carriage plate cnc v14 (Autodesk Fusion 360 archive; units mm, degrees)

design "carriage plate cnc" references "Cup Holder"
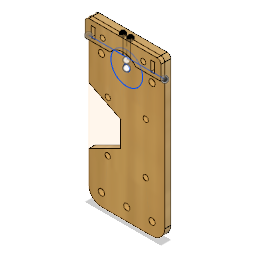
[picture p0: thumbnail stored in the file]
parameter "material" = 5
parameter "tool_dia" = 3.175
sketch "Sketch1" plane through (0, 0, 0) normal (0, 0, 1) x axis (1, 0, 0)
  line L1 (-20, 57.5) -> (20, 57.5)
  line L2 (-30, -47.5) -> (-30, 47.5)
  line L3 (20, -57.5) -> (-20, -57.5)
  line L4 (30, 47.5) -> (30, -47.5)
  line L5 (0, 22.5) -> (0, 1.75)
  line L6 (22.5, 0) -> (1.75, 0)
  circle C1 centre (0, 47.5) radius 2.46
  circle C2 centre (20, -47.5) radius 2.46
  circle C3 centre (0, -47.5) radius 2.46
  circle C4 centre (-20, -47.5) radius 2.46
  circle C5 centre (20, 47.5) radius 2.46
  circle C6 centre (-20, 47.5) radius 2.46
  arc A1 centre (20, 47.5) radius 10 clockwise from (20, 57.5) to (30, 47.5)
  arc A2 centre (-20, 47.5) radius 10 clockwise from (-30, 47.5) to (-20, 57.5)
  arc A3 centre (-20, -47.5) radius 10 clockwise from (-20, -57.5) to (-30, -47.5)
  arc A4 centre (20, -47.5) radius 10 clockwise from (30, -47.5) to (20, -57.5)
  circle C7 centre (-15, -20) radius 2
  circle C8 centre (15, -20) radius 2
  circle C9 centre (-15, 20) radius 2
  circle C10 centre (15, 20) radius 2
  point P1 (0, 0)
  point P2 (0, 0)
  point P4 (20, -47.5)
  point P5 (0, -47.5)
  point P6 (-20, -47.5)
  point P3 (0, 47.5)
  point P7 (20, 47.5)
  point P8 (-20, 47.5)
  point P9 (0, 0)
  point P10 (20, 57.5)
  point P16 (-30, -47.5)
  point P22 (-30, -47.5)
  point P23 (20, 57.5)
  point P24 (-15, -20)
  coincident P1 P2
  horizontal P4 P5
  horizontal P5 P6
  equal C2 C3
  equal C3 C4
  equal C4 C6
  equal C1 C6
  equal C1 C5
  vertical P2 P3
  horizontal P3 P7
  horizontal P3 P8
  vertical P1 P5
  vertical P4 P7
  vertical P6 P8
  perpendicular L1 L2
  parallel L1 L3
  parallel L2 L4
  horizontal L1
  coincident P1 P9
  tangent L4 A1
  coincident L1 P10
  tangent L2 A2
  tangent L3 A3
  coincident L2 P16
  tangent L3 A4
  coincident A3 P22
  coincident A1 P23
  tangent L1 A2
  tangent L1 A1
  tangent L4 A4
  tangent L2 A3
  equal A3 A4
  equal A1 A4
  equal A1 A2
  symmetric C7 L5 C8
  symmetric C7 L6 C9
  symmetric C8 L6 C10
  dimension "d3_1" distance P2 P3 = 47.5 (= "( 95 / 2 ) * 1 mm")
  dimension "d4_1" distance P1 P5 = 47.5 (= "d3_1")
  dimension "d5_1" distance P4 P5 = 20
  dimension "d6_1" distance P5 P6 = 20 (= "d5_1")
  dimension "d7" diameter C1 = 4.92
  dimension "d8_1" distance P7 L1 = 10
  dimension "d9_1" distance P7 L4 = 10
  dimension "d10_1" distance P4 L3 = 10 (= "d8_1")
  dimension "d12_1" distance P6 L2 = 10 (= "d8_1")
  dimension "d13_1" radius A2 = 10
  dimension "d18_1" diameter C7 = 4
  dimension "d22" distance P9 P24 = 20
  dimension "d23" distance P2 P24 = 15
extrude "Extrude1" new body sketch "Sketch1" profile of C1 C2 C3 C4 C5 C6 L1 L2 L3 L4 A1 A2 A3 A4 C7 C8 C9 C10 along normal blind 5
sketch "Sketch1" plane through (0, 0, 5) normal (0, 0, 1) x axis (-1, 0, 0)
  line L1 (-30, -47.5) -> (-30, 47.5)
  line L2 (20, -57.5) -> (-20, -57.5)
  line L3 (30, 47.5) -> (30, -47.5)
  line L4 (-20, 57.5) -> (20, 57.5)
  line L5 (24.7343, -47.5) -> (22.3671, -51.6)
  line L6 (22.3671, -43.4) -> (24.7343, -47.5)
  line L7 (17.6329, -43.4) -> (22.3671, -43.4)
  line L8 (15.2657, -47.5) -> (17.6329, -43.4)
  line L9 (17.6329, -51.6) -> (15.2657, -47.5)
  line L10 (22.3671, -51.6) -> (17.6329, -51.6)
  line L11 (4.7343, -47.5) -> (2.3671, -51.6)
  line L12 (2.3671, -43.4) -> (4.7343, -47.5)
  line L13 (-2.3671, -43.4) -> (2.3671, -43.4)
  line L14 (-4.7343, -47.5) -> (-2.3671, -43.4)
  line L15 (-2.3671, -51.6) -> (-4.7343, -47.5)
  line L16 (2.3671, -51.6) -> (-2.3671, -51.6)
  line L17 (-15.2657, -47.5) -> (-17.6329, -51.6)
  line L18 (-17.6329, -43.4) -> (-15.2657, -47.5)
  line L19 (-22.3671, -43.4) -> (-17.6329, -43.4)
  line L20 (-24.7343, -47.5) -> (-22.3671, -43.4)
  line L21 (-22.3671, -51.6) -> (-24.7343, -47.5)
  line L22 (-17.6329, -51.6) -> (-22.3671, -51.6)
  line L23 (24.7343, 47.5) -> (22.3671, 43.4)
  line L24 (22.3671, 51.6) -> (24.7343, 47.5)
  line L25 (17.6329, 51.6) -> (22.3671, 51.6)
  line L26 (15.2657, 47.5) -> (17.6329, 51.6)
  line L27 (17.6329, 43.4) -> (15.2657, 47.5)
  line L28 (22.3671, 43.4) -> (17.6329, 43.4)
  line L29 (4.7343, 47.5) -> (2.3671, 43.4)
  line L30 (2.3671, 51.6) -> (4.7343, 47.5)
  line L31 (-2.3671, 51.6) -> (2.3671, 51.6)
  line L32 (-4.7343, 47.5) -> (-2.3671, 51.6)
  line L33 (-2.3671, 43.4) -> (-4.7343, 47.5)
  line L34 (2.3671, 43.4) -> (-2.3671, 43.4)
  line L35 (-15.2657, 47.5) -> (-17.6329, 43.4)
  line L36 (-17.6329, 51.6) -> (-15.2657, 47.5)
  line L37 (-22.3671, 51.6) -> (-17.6329, 51.6)
  line L38 (-24.7343, 47.5) -> (-22.3671, 51.6)
  line L39 (-22.3671, 43.4) -> (-24.7343, 47.5)
  line L40 (-17.6329, 43.4) -> (-22.3671, 43.4)
  circle C1 centre (0, 47.5) radius 2.46
  circle C2 centre (0, -47.5) radius 2.46
  circle C3 centre (-20, 47.5) radius 2.46
  circle C4 centre (20, 47.5) radius 2.46
  circle C5 centre (-15, -20) radius 2
  circle C6 centre (15, 20) radius 2
  circle C7 centre (20, -47.5) radius 2.46
  circle C8 centre (15, -20) radius 2
  circle C9 centre (-15, 20) radius 2
  circle C10 centre (-20, -47.5) radius 2.46
  arc A1 centre (-20, 47.5) radius 10 clockwise from (-30, 47.5) to (-20, 57.5)
  arc A2 centre (-20, -47.5) radius 10 clockwise from (-20, -57.5) to (-30, -47.5)
  arc A3 centre (20, -47.5) radius 10 clockwise from (30, -47.5) to (20, -57.5)
  arc A4 centre (20, 47.5) radius 10 clockwise from (20, 57.5) to (30, 47.5)
  point P8 (20, -47.5)
  point P26 (20, -47.5)
  point P3 (0, -47.5)
  point P33 (0, -47.5)
  point P11 (-20, -47.5)
  point P40 (-20, -47.5)
  point P5 (20, 47.5)
  point P47 (20, 47.5)
  point P2 (0, 47.5)
  point P54 (0, 47.5)
  point P4 (-20, 47.5)
  point P61 (-20, 47.5)
  coincident P8 P26
  coincident P3 P33
  coincident P11 P40
  coincident P5 P47
  coincident P2 P54
  coincident P4 P61
  dimension "d1" distance P26 L10 = 4.1
  dimension "d2" distance P33 L16 = 4.1 (= "d1")
  dimension "d3" distance P40 L22 = 4.1 (= "d2")
  dimension "d4" distance P47 L28 = 4.1 (= "d1")
  dimension "d5" distance P54 L34 = 4.1 (= "d1")
  dimension "d6" distance P61 L40 = 4.1 (= "d1")
extrude "Extrude1" new body sketch "Sketch1" profile of C5 C6 C8 C9 A1 L1 A2 L2 A3 L3 A4 L4 L5 L6 L7 L8 L9 L10 L11 L12 L13 L14 L15 L16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 along normal blind 5 (= "material")
extrude "Extrude2" add sketch "Sketch1" profile of C1 C2 C3 C4 C7 C10 L5 L6 L7 L8 L9 L10 L11 L12 L13 L14 L15 L16 L17 L18 L19 L20 L21 L22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 along normal blind 1
extrude "Extrude3" add sketch "Sketch1" profile of C5 C6 C8 C9 along normal blind 1
sketch "Sketch2" plane through (0, 0, 10) normal (0, 0, 1) x axis (1, 0, 0)
  line L1 (22.3671, 51.6) -> (17.6329, 51.6)
  line L2 (24.7343, 47.5) -> (22.3671, 51.6)
  line L3 (22.3671, 43.4) -> (24.7343, 47.5)
  line L4 (17.6329, 43.4) -> (22.3671, 43.4)
  line L5 (15.2657, 47.5) -> (17.6329, 43.4)
  line L6 (17.6329, 51.6) -> (15.2657, 47.5)
  line L7 (-17.6329, 51.6) -> (-22.3671, 51.6)
  line L8 (-15.2657, 47.5) -> (-17.6329, 51.6)
  line L9 (-17.6329, 43.4) -> (-15.2657, 47.5)
  line L10 (-22.3671, 43.4) -> (-17.6329, 43.4)
  line L11 (-24.7343, 47.5) -> (-22.3671, 43.4)
  line L12 (-22.3671, 51.6) -> (-24.7343, 47.5)
  line L13 (22.3671, -43.4) -> (17.6329, -43.4)
  line L14 (24.7343, -47.5) -> (22.3671, -43.4)
  line L15 (22.3671, -51.6) -> (24.7343, -47.5)
  line L16 (17.6329, -51.6) -> (22.3671, -51.6)
  line L17 (15.2657, -47.5) -> (17.6329, -51.6)
  line L18 (17.6329, -43.4) -> (15.2657, -47.5)
  line L19 (-17.6329, -43.4) -> (-22.3671, -43.4)
  line L20 (-15.2657, -47.5) -> (-17.6329, -43.4)
  line L21 (-17.6329, -51.6) -> (-15.2657, -47.5)
  line L22 (-22.3671, -51.6) -> (-17.6329, -51.6)
  line L23 (-24.7343, -47.5) -> (-22.3671, -51.6)
  line L24 (-22.3671, -43.4) -> (-24.7343, -47.5)
  line L25 (2.3671, -43.4) -> (-2.3671, -43.4)
  line L26 (4.7343, -47.5) -> (2.3671, -43.4)
  line L27 (2.3671, -51.6) -> (4.7343, -47.5)
  line L28 (-2.3671, -51.6) -> (2.3671, -51.6)
  line L29 (-4.7343, -47.5) -> (-2.3671, -51.6)
  line L30 (-2.3671, -43.4) -> (-4.7343, -47.5)
  line L31 (2.3671, 51.6) -> (-2.3671, 51.6)
  line L32 (4.7343, 47.5) -> (2.3671, 51.6)
  line L33 (2.3671, 43.4) -> (4.7343, 47.5)
  line L34 (-2.3671, 43.4) -> (2.3671, 43.4)
  line L35 (-4.7343, 47.5) -> (-2.3671, 43.4)
  line L36 (-2.3671, 51.6) -> (-4.7343, 47.5)
  line L37 (20, -57.5) -> (-20, -57.5)
  line L38 (30, 47.5) -> (30, -47.5)
  line L39 (-20, 57.5) -> (20, 57.5)
  line L40 (-30, -47.5) -> (-30, 47.5)
  line L41 (30, 30) -> (-30, 30)
  line L42 (30, -30) -> (-30, -30)
  circle C1 centre (-15, 20) radius 2
  circle C2 centre (15, 20) radius 2
  circle C3 centre (-15, -20) radius 2
  circle C4 centre (15, -20) radius 2
  arc A1 centre (20, -47.5) radius 10 clockwise from (30, -47.5) to (20, -57.5)
  arc A2 centre (20, 47.5) radius 10 clockwise from (20, 57.5) to (30, 47.5)
  arc A3 centre (-20, 47.5) radius 10 clockwise from (-30, 47.5) to (-20, 57.5)
  arc A4 centre (-20, -47.5) radius 10 clockwise from (-20, -57.5) to (-30, -47.5)
  point P54 (-30, 30)
  point P55 (30, 30)
  point P56 (-30, -30)
  point P57 (30, -30)
  point P1 (0, 0)
  coincident L40 P54
  coincident L38 P55
  perpendicular L38 L41
  coincident L40 P56
  coincident L38 P57
  perpendicular L38 L42
  dimension "d15" distance P1 L42 = 30
  dimension "d16" distance P1 L41 = 30
extrude "Extrude4" add sketch "Sketch2" profile of L20 C1 C2 C3 C4 against normal blind 4
sketch "Sketch3" plane through (0, 0, 0) normal (0, 0, -1) x axis (1, 0, 0)
  line L1 (-20, 57.5) -> (20, 57.5)
  line L2 (-30, -47.5) -> (-30, 47.5)
  line L3 (20, -57.5) -> (-20, -57.5)
  line L4 (30, 47.5) -> (30, -47.5)
  circle C1 centre (0, 47.5) radius 2.46
  circle C2 centre (0, -47.5) radius 2.46
  circle C3 centre (20, 47.5) radius 2.46
  circle C4 centre (-20, 47.5) radius 2.46
  circle C5 centre (15, -20) radius 2
  circle C6 centre (-15, 20) radius 2
  circle C7 centre (-20, -47.5) radius 2.46
  circle C8 centre (-15, -20) radius 2
  circle C9 centre (15, 20) radius 2
  circle C10 centre (20, -47.5) radius 2.46
  arc A1 centre (20, 47.5) radius 10 clockwise from (20, 57.5) to (30, 47.5)
  arc A2 centre (-20, 47.5) radius 10 clockwise from (-30, 47.5) to (-20, 57.5)
  arc A3 centre (-20, -47.5) radius 10 clockwise from (-20, -57.5) to (-30, -47.5)
  arc A4 centre (20, -47.5) radius 10 clockwise from (30, -47.5) to (20, -57.5)
extrude "Extrude5" new body sketch "Sketch3" profile of C5 C6 C8 C9 against normal blind 1
combine "Combine1"
sketch "Sketch4" plane through (0, 0, 5) normal (0, 0, 1) x axis (-1, 0, 0)
  circle C1 centre (15, -20) radius 2.1
  circle C2 centre (-15, -20) radius 2.1
  circle C3 centre (15, 20) radius 2.1
  circle C4 centre (-15, 20) radius 2.1
  dimension "d21" diameter C1 = 4.2
  dimension "d26" diameter C2 = 4.2
  dimension "d27" diameter C3 = 4.2
  dimension "d28" diameter C4 = 4.2
extrude "Extrude6" cut sketch "Sketch4" + "Sketch1" profile of S2:C5 S1:C1 S1:C3 S1:C4 blind -4
extrude "Extrude7" cut sketch "Sketch4" profile of C2 against normal blind 4
sketch "Sketch5" plane through (0, 0, 5) normal (0, 0, 1) x axis (1, 0, 0)
  line L1 (30, 47.5) -> (30, -47.5)
  line L2 (-20, 57.5) -> (20, 57.5)
  line L3 (-30, -47.5) -> (-30, 47.5)
  line L4 (20, -57.5) -> (-20, -57.5)
  line L5 (-30, 47.5) -> (30, 47.5)
  line L6 (-30, 69.5) -> (-30, 47.5)
  line L7 (30, 69.5) -> (-30, 69.5)
  line L8 (30, 47.5) -> (30, 69.5)
  line L9 (25, 65.5) -> (22, 65.5)
  line L10 (25, 57.5) -> (25, 65.5)
  line L11 (22, 57.5) -> (25, 57.5)
  line L12 (22, 65.5) -> (22, 57.5)
  line L13 (0, 57.5) -> (0, 69.5)
  line L14 (-25, 57.5) -> (-25, 65.5)
  line L15 (-22, 57.5) -> (-25, 57.5)
  line L16 (-25, 65.5) -> (-22, 65.5)
  line L17 (-22, 65.5) -> (-22, 57.5)
  line L18 (4, 57.5) -> (10, 57.5)
  line L19 (4, 65.5) -> (4, 57.5)
  line L20 (10, 65.5) -> (4, 65.5)
  line L21 (10, 57.5) -> (10, 65.5)
  line L22 (22, 61.5) -> (10, 61.5)
  line L23 (-4, 65.5) -> (-4, 57.5)
  line L24 (-10, 65.5) -> (-4, 65.5)
  line L25 (-4, 57.5) -> (-10, 57.5)
  line L26 (-10, 57.5) -> (-10, 65.5)
  circle C1 centre (15, 20) radius 2.1
  circle C2 centre (-15, 20) radius 2.1
  circle C3 centre (-15, -20) radius 2.1
  circle C4 centre (15, -20) radius 2.1
  circle C5 centre (0, -47.5) radius 2.46
  circle C6 centre (20, -47.5) radius 2.46
  circle C7 centre (0, 47.5) radius 2.46
  circle C8 centre (-20, -47.5) radius 2.46
  circle C9 centre (20, 47.5) radius 2.46
  circle C10 centre (-20, 47.5) radius 2.46
  arc A1 centre (20, -47.5) radius 10 clockwise from (30, -47.5) to (20, -57.5)
  arc A2 centre (20, 47.5) radius 10 clockwise from (20, 57.5) to (30, 47.5)
  arc A3 centre (-20, 47.5) radius 10 clockwise from (-30, 47.5) to (-20, 57.5)
  arc A4 centre (-20, -47.5) radius 10 clockwise from (-20, -57.5) to (-30, -47.5)
  circle C11 centre (16, 61.5) radius 2
  circle C12 centre (-16, 61.5) radius 2
  point P14 (30, 47.5)
  point P20 (30, 47.5)
  point P28 (0, 69.5)
  point P29 (0, 57.5)
  point P24 (22, 65.5)
  point P33 (-22, 65.5)
  point P25 (25, 65.5)
  point P30 (-25, 65.5)
  point P26 (25, 57.5)
  point P31 (-25, 57.5)
  point P27 (22, 57.5)
  point P32 (-22, 57.5)
  point P34 (10, 57.5)
  point P38 (10, 61.5)
  point P39 (22, 61.5)
  point P40 (16, 61.5)
  point P45 (-10, 57.5)
  point P35 (4, 57.5)
  point P42 (-4, 57.5)
  point P36 (4, 65.5)
  point P43 (-4, 65.5)
  point P37 (10, 65.5)
  point P44 (-10, 65.5)
  point P23 (30, 69.5)
  horizontal L5
  vertical L6
  horizontal L7
  vertical L8
  coincident P14 P20
  collinear L3 L6
  horizontal L9
  vertical L10
  horizontal L11
  vertical L12
  collinear L2 L11
  midpoint L7 P28
  midpoint L2 P29
  symmetric P24 L13 P33
  symmetric P25 L13 P30
  symmetric P26 L13 P31
  symmetric P27 L13 P32
  horizontal L18
  vertical L19
  horizontal L20
  vertical L21
  coincident L2 P34
  midpoint L21 P38
  midpoint L12 P39
  midpoint L22 P40
  symmetric L13 P34 P45
  symmetric L13 P35 P42
  symmetric L13 P36 P43
  symmetric L13 P37 P44
  symmetric L13 C11 C12
  dimension "d33" distance P20 P23 = 22
  dimension "d34" distance P24 P25 = 3
  dimension "d35" distance P24 P27 = 8
  dimension "d36" distance L8 L10 = 5
  dimension "d37" distance P34 P35 = 6
  dimension "d38" distance P34 P37 = 8
  dimension "d39" distance L12 L21 = 12
  dimension "d40" diameter C11 = 4
extrude "Extrude8" add sketch "Sketch5" profile of A2 L2 A3 L6 L7 L8 L9 L10 L11 L12 L14 L15 L16 L17 L19 L20 L21 C11 C12 L23 L24 L26 against normal blind 5
fillet "Fillet1" radius 3
sketch "Sketch6" plane through (0, 0, 5) normal (0, 0, 1) x axis (1, 0, 0)
  line L1 (-30, -47.5) -> (-30, 66.5)
  line L2 (20, -57.5) -> (-20, -57.5)
  line L3 (30, 66.5) -> (30, -47.5)
  line L4 (-27, 69.5) -> (27, 69.5)
  line L5 (4, 57.5) -> (10, 57.5)
  line L6 (4, 65.5) -> (4, 57.5)
  line L7 (10, 65.5) -> (4, 65.5)
  line L8 (10, 57.5) -> (10, 65.5)
  line L9 (-22, 57.5) -> (-22, 65.5)
  line L10 (-25, 57.5) -> (-22, 57.5)
  line L11 (-25, 65.5) -> (-25, 57.5)
  line L12 (-22, 65.5) -> (-25, 65.5)
  line L13 (22, 57.5) -> (25, 57.5)
  line L14 (22, 65.5) -> (22, 57.5)
  line L15 (25, 65.5) -> (22, 65.5)
  line L16 (25, 57.5) -> (25, 65.5)
  line L17 (-10, 65.5) -> (-10, 57.5)
  line L18 (-4, 65.5) -> (-10, 65.5)
  line L19 (-4, 57.5) -> (-4, 65.5)
  line L20 (-10, 57.5) -> (-4, 57.5)
  line L21 (-3, 54.8814) -> (-30, 54.8814)
  line L22 (-3, 69.5) -> (-3, 54.8814)
  line L23 (3, 54.8814) -> (3, 69.5)
  line L24 (30, 54.8814) -> (3, 54.8814)
  line L25 (0, 53) -> (0, 69.5)
  line L26 (-3, 54.8814) -> (3, 54.8814)
  arc A1 centre (-27, 66.5) radius 3 clockwise from (-30, 66.5) to (-27, 69.5)
  arc A2 centre (-20, -47.5) radius 10 clockwise from (-20, -57.5) to (-30, -47.5)
  arc A3 centre (20, -47.5) radius 10 clockwise from (30, -47.5) to (20, -57.5)
  arc A4 centre (27, 66.5) radius 3 clockwise from (27, 69.5) to (30, 66.5)
  circle C1 centre (-16, 61.5) radius 2
  circle C2 centre (16, 61.5) radius 2
  circle C3 centre (15, 20) radius 2.1
  circle C4 centre (-15, 20) radius 2.1
  circle C5 centre (-15, -20) radius 2.1
  circle C6 centre (15, -20) radius 2.1
  circle C7 centre (0, -47.5) radius 2.46
  circle C8 centre (20, -47.5) radius 2.46
  circle C9 centre (0, 47.5) radius 2.46
  circle C10 centre (-20, -47.5) radius 2.46
  circle C11 centre (20, 47.5) radius 2.46
  circle C12 centre (-20, 47.5) radius 2.46
  point P40 (-30, 54.8814)
  point P42 (-3, 69.5)
  point P43 (3, 69.5)
  point P45 (30, 54.8814)
  point P46 (0, 69.5)
  coincident L1 P40
  perpendicular L1 L21
  coincident L4 P42
  perpendicular L4 L22
  coincident L4 P43
  perpendicular L4 L23
  coincident L3 P45
  perpendicular L3 L24
  midpoint L4 P46
  perpendicular L4 L25
  perpendicular L22 L26
  dimension "d44" distance L1 L22 = 27
  dimension "d45" distance L3 L23 = 27
extrude "Extrude9" new body sketch "Sketch6" profile of A1 L1 L3 A4 L4 L5 L6 L7 L8 L9 L10 L11 L12 C1 L13 L14 L15 L16 C2 L17 L18 L19 L20 L21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 along normal blind 5
sketch "Sketch1" plane through (0, 0, 10) normal (0, 0, 1) x axis (1, 0, 0)
  line L1 (10, 65.5) -> (4, 65.5)
  line L2 (10, 57.5) -> (10, 65.5)
  line L3 (4, 57.5) -> (10, 57.5)
  line L4 (4, 65.5) -> (4, 57.5)
  line L5 (-4, 57.5) -> (-4, 65.5)
  line L6 (-10, 57.5) -> (-4, 57.5)
  line L7 (-10, 65.5) -> (-10, 57.5)
  line L8 (-4, 65.5) -> (-10, 65.5)
  line L9 (25, 65.5) -> (22, 65.5)
  line L10 (25, 57.5) -> (25, 65.5)
  line L11 (22, 57.5) -> (25, 57.5)
  line L12 (22, 65.5) -> (22, 57.5)
  line L13 (-25, 65.5) -> (-25, 57.5)
  line L14 (-22, 65.5) -> (-25, 65.5)
  line L15 (-22, 57.5) -> (-22, 65.5)
  line L16 (-25, 57.5) -> (-22, 57.5)
  line L17 (30, 66.5) -> (30, 54.8814)
  line L18 (-27, 69.5) -> (27, 69.5)
  line L19 (-30, 54.8814) -> (-30, 66.5)
  line L20 (30, 54.8814) -> (-30, 54.8814)
  circle C1 centre (16, 61.5) radius 2
  circle C2 centre (-16, 61.5) radius 2
  arc A1 centre (27, 66.5) radius 3 clockwise from (27, 69.5) to (30, 66.5)
  arc A2 centre (-27, 66.5) radius 3 clockwise from (-30, 66.5) to (-27, 69.5)
sketch "Sketch2" plane through (0, 0, 5) normal (0, 0, 1) x axis (1, 0, 0)
  line L1 (-30, -47.5) -> (-30, 66.5)
  line L2 (20, -57.5) -> (-20, -57.5)
  line L3 (30, 66.5) -> (30, -47.5)
  line L4 (-27, 69.5) -> (27, 69.5)
  line L5 (4, 57.5) -> (10, 57.5)
  line L6 (4, 65.5) -> (4, 57.5)
  line L7 (10, 65.5) -> (4, 65.5)
  line L8 (10, 57.5) -> (10, 65.5)
  line L9 (22, 57.5) -> (25, 57.5)
  line L10 (22, 65.5) -> (22, 57.5)
  line L11 (25, 65.5) -> (22, 65.5)
  line L12 (25, 57.5) -> (25, 65.5)
  line L13 (-22, 57.5) -> (-22, 65.5)
  line L14 (-25, 57.5) -> (-22, 57.5)
  line L15 (-25, 65.5) -> (-25, 57.5)
  line L16 (-22, 65.5) -> (-25, 65.5)
  line L17 (-10, 65.5) -> (-10, 57.5)
  line L18 (-4, 65.5) -> (-10, 65.5)
  line L19 (-4, 57.5) -> (-4, 65.5)
  line L20 (-10, 57.5) -> (-4, 57.5)
  arc A1 centre (-27, 66.5) radius 3 clockwise from (-30, 66.5) to (-27, 69.5)
  arc A2 centre (-20, -47.5) radius 10 clockwise from (-20, -57.5) to (-30, -47.5)
  arc A3 centre (20, -47.5) radius 10 clockwise from (30, -47.5) to (20, -57.5)
  arc A4 centre (27, 66.5) radius 3 clockwise from (27, 69.5) to (30, 66.5)
  circle C1 centre (16, 61.5) radius 2
  circle C2 centre (-16, 61.5) radius 2
  circle C3 centre (15, 20) radius 2.1
  circle C4 centre (-15, 20) radius 2.1
  circle C5 centre (-15, -20) radius 2.1
  circle C6 centre (15, -20) radius 2.1
  circle C7 centre (0, -47.5) radius 2.46
  circle C8 centre (20, -47.5) radius 2.46
  circle C9 centre (0, 47.5) radius 2.46
  circle C10 centre (-20, -47.5) radius 2.46
  circle C11 centre (20, 47.5) radius 2.46
  circle C12 centre (-20, 47.5) radius 2.46
component_insert "Component Insert"
sketch "Sketch3" plane through (0, 0, -4) normal (0, 0, 1) x axis (-1, 0, 0)
  line L1 (30, 22.5) -> (5, 10)
  line L2 (30, 47.5) -> (30, 22.5)
  line L3 (-20, 57.5) -> (20, 57.5)
  line L4 (-30, -47.5) -> (-30, 47.5)
  line L5 (20, -57.5) -> (-20, -57.5)
  line L6 (30, -22.5) -> (30, -47.5)
  line L7 (5, -10) -> (30, -22.5)
  line L8 (5, 10) -> (5, -10)
  circle C1 centre (0, -47.5) radius 2.46
  circle C2 centre (20, -47.5) radius 2.46
  circle C3 centre (-20, 47.5) radius 2.46
  circle C4 centre (0, 47.5) radius 2.46
  circle C5 centre (-20, -47.5) radius 2.46
  circle C6 centre (20, 47.5) radius 2.46
  arc A1 centre (20, 47.5) radius 10 clockwise from (20, 57.5) to (30, 47.5)
  arc A2 centre (-20, 47.5) radius 10 clockwise from (-30, 47.5) to (-20, 57.5)
  arc A3 centre (-20, -47.5) radius 10 clockwise from (-20, -57.5) to (-30, -47.5)
  arc A4 centre (20, -47.5) radius 10 clockwise from (30, -47.5) to (20, -57.5)
sketch "Sketch4" plane through (0, 0, -4) normal (0, 0, 1) x axis (-1, 0, 0)
  line L1 (30, 22.5) -> (5, 10)
  line L2 (30, 47.5) -> (30, 22.5)
  line L3 (-20, 57.5) -> (20, 57.5)
  line L4 (-30, -47.5) -> (-30, 47.5)
  line L5 (20, -57.5) -> (-20, -57.5)
  line L6 (30, -22.5) -> (30, -47.5)
  line L7 (5, -10) -> (30, -22.5)
  line L8 (5, 10) -> (5, -10)
  line L9 (30, 22.5) -> (30, -22.5)
  circle C1 centre (0, -47.5) radius 2.46
  circle C2 centre (20, -47.5) radius 2.46
  circle C3 centre (-20, 47.5) radius 2.46
  circle C4 centre (0, 47.5) radius 2.46
  circle C5 centre (-20, -47.5) radius 2.46
  circle C6 centre (20, 47.5) radius 2.46
  arc A1 centre (20, 47.5) radius 10 clockwise from (20, 57.5) to (30, 47.5)
  arc A2 centre (-20, 47.5) radius 10 clockwise from (-30, 47.5) to (-20, 57.5)
  arc A3 centre (-20, -47.5) radius 10 clockwise from (-20, -57.5) to (-30, -47.5)
  arc A4 centre (20, -47.5) radius 10 clockwise from (30, -47.5) to (20, -57.5)
  point P18 (30, -22.5)
  point P20 (30, -22.5)
  point P9 (30, 22.5)
  point P21 (30, 22.5)
  coincident P18 P20
  coincident P9 P21
extrude "Extrude10" cut sketch "Sketch4" profile of L1 L7 L8 L9 along normal blind 35
sketch "Sketch5" plane through (0, 0, 5) normal (0, 0, 1) x axis (1, 0, 0)
  line L1 (-10, 65.5) -> (-10, 57.5)
  line L2 (-4, 65.5) -> (-10, 65.5)
  line L3 (-4, 57.5) -> (-4, 65.5)
  line L4 (-10, 57.5) -> (-4, 57.5)
  line L5 (-22, 57.5) -> (-22, 65.5)
  line L6 (-25, 57.5) -> (-22, 57.5)
  line L7 (-25, 65.5) -> (-25, 57.5)
  line L8 (-22, 65.5) -> (-25, 65.5)
  line L9 (22, 57.5) -> (25, 57.5)
  line L10 (22, 65.5) -> (22, 57.5)
  line L11 (25, 65.5) -> (22, 65.5)
  line L12 (25, 57.5) -> (25, 65.5)
  line L13 (4, 57.5) -> (10, 57.5)
  line L14 (4, 65.5) -> (4, 57.5)
  line L15 (10, 65.5) -> (4, 65.5)
  line L16 (10, 57.5) -> (10, 65.5)
  line L17 (-5, 10) -> (-30, 22.5)
  line L18 (-5, -10) -> (-5, 10)
  line L19 (-30, -22.5) -> (-5, -10)
  line L20 (-30, -47.5) -> (-30, -22.5)
  line L21 (20, -57.5) -> (-20, -57.5)
  line L22 (30, 66.5) -> (30, -47.5)
  line L23 (-27, 69.5) -> (27, 69.5)
  line L24 (-30, 22.5) -> (-30, 66.5)
  circle C1 centre (-20, 47.5) radius 2.46
  circle C2 centre (20, 47.5) radius 2.46
  circle C3 centre (-20, -47.5) radius 2.46
  circle C4 centre (0, 47.5) radius 2.46
  circle C5 centre (20, -47.5) radius 2.46
  circle C6 centre (0, -47.5) radius 2.46
  circle C7 centre (15, -20) radius 2.1
  circle C8 centre (-15, -20) radius 2.1
  circle C9 centre (-15, 20) radius 2.1
  circle C10 centre (15, 20) radius 2.1
  circle C11 centre (-16, 61.5) radius 2
  circle C12 centre (16, 61.5) radius 2
  arc A1 centre (-20, -47.5) radius 10 clockwise from (-20, -57.5) to (-30, -47.5)
  arc A2 centre (20, -47.5) radius 10 clockwise from (30, -47.5) to (20, -57.5)
  arc A3 centre (27, 66.5) radius 3 clockwise from (27, 69.5) to (30, 66.5)
  arc A4 centre (-27, 66.5) radius 3 clockwise from (-30, 66.5) to (-27, 69.5)
sketch "Sketch6" plane through (0, 0, 5) normal (0, 0, 1) x axis (1, 0, 0)
  line L1 (-10, 65.5) -> (-10, 57.5)
  line L2 (-4, 65.5) -> (-10, 65.5)
  line L3 (-4, 57.5) -> (-4, 65.5)
  line L4 (-10, 57.5) -> (-4, 57.5)
  line L5 (-22, 57.5) -> (-22, 65.5)
  line L6 (-25, 57.5) -> (-22, 57.5)
  line L7 (-25, 65.5) -> (-25, 57.5)
  line L8 (-22, 65.5) -> (-25, 65.5)
  line L9 (22, 57.5) -> (25, 57.5)
  line L10 (22, 65.5) -> (22, 57.5)
  line L11 (25, 65.5) -> (22, 65.5)
  line L12 (25, 57.5) -> (25, 65.5)
  line L13 (4, 57.5) -> (10, 57.5)
  line L14 (4, 65.5) -> (4, 57.5)
  line L15 (10, 65.5) -> (4, 65.5)
  line L16 (10, 57.5) -> (10, 65.5)
  line L17 (-5, 10) -> (-30, 22.5)
  line L18 (-5, -10) -> (-5, 10)
  line L19 (-30, -22.5) -> (-5, -10)
  line L20 (-30, -47.5) -> (-30, -22.5)
  line L21 (20, -57.5) -> (-20, -57.5)
  line L22 (30, 66.5) -> (30, -47.5)
  line L23 (-27, 69.5) -> (27, 69.5)
  line L24 (-30, 22.5) -> (-30, 66.5)
  line L25 (30, 54.8814) -> (3, 54.8814)
  line L26 (-3, 54.8814) -> (3, 54.8814)
  line L27 (-3, 54.8814) -> (-30, 54.8814)
  circle C1 centre (-20, 47.5) radius 2.46
  circle C2 centre (20, 47.5) radius 2.46
  circle C3 centre (-20, -47.5) radius 2.46
  circle C4 centre (0, 47.5) radius 2.46
  circle C5 centre (20, -47.5) radius 2.46
  circle C6 centre (0, -47.5) radius 2.46
  circle C7 centre (15, -20) radius 2.1
  circle C8 centre (-15, -20) radius 2.1
  circle C9 centre (-15, 20) radius 2.1
  circle C10 centre (15, 20) radius 2.1
  circle C11 centre (-16, 61.5) radius 2
  circle C12 centre (16, 61.5) radius 2
  arc A1 centre (-20, -47.5) radius 10 clockwise from (-20, -57.5) to (-30, -47.5)
  arc A2 centre (20, -47.5) radius 10 clockwise from (30, -47.5) to (20, -57.5)
  arc A3 centre (27, 66.5) radius 3 clockwise from (27, 69.5) to (30, 66.5)
  arc A4 centre (-27, 66.5) radius 3 clockwise from (-30, 66.5) to (-27, 69.5)
  circle C13 centre (0, 47.5) radius 2.46
  circle C14 centre (0, 47.5) radius 12.5
  concentric C13 C14
  dimension "d51" diameter C14 = 25
extrude "Extrude11" cut sketch "Sketch6" profile of L3 L4 C4 L13 L14 C13 C14 along normal blind 10
sketch "Sketch7" plane through (0, 0, 10) normal (0, 0, 1) x axis (1, 0, 0)
  line L1 (4, 65.5) -> (4, 59.3427)
  line L2 (10, 65.5) -> (4, 65.5)
  line L3 (10, 57.5) -> (10, 65.5)
  line L4 (7.5, 57.5) -> (10, 57.5)
  line L5 (30, 54.8814) -> (10.0878, 54.8814)
  line L6 (30, 66.5) -> (30, 54.8814)
  line L7 (-27, 69.5) -> (27, 69.5)
  line L8 (-30, 54.8814) -> (-30, 66.5)
  line L9 (-10.0878, 54.8814) -> (-30, 54.8814)
  line L10 (-10, 57.5) -> (-7.5, 57.5)
  line L11 (-10, 65.5) -> (-10, 57.5)
  line L12 (-4, 65.5) -> (-10, 65.5)
  line L13 (-4, 59.3427) -> (-4, 65.5)
  line L14 (-25, 65.5) -> (-25, 57.5)
  line L15 (-22, 65.5) -> (-25, 65.5)
  line L16 (-22, 57.5) -> (-22, 65.5)
  line L17 (-25, 57.5) -> (-22, 57.5)
  line L18 (25, 65.5) -> (22, 65.5)
  line L19 (25, 57.5) -> (25, 65.5)
  line L20 (22, 57.5) -> (25, 57.5)
  line L21 (22, 65.5) -> (22, 57.5)
  arc A1 centre (0, 47.5) radius 12.5 clockwise from (-4, 59.3427) to (4, 59.3427)
  arc A2 centre (0, 47.5) radius 12.5 clockwise from (7.5, 57.5) to (10.0878, 54.8814)
  arc A3 centre (27, 66.5) radius 3 clockwise from (27, 69.5) to (30, 66.5)
  arc A4 centre (-27, 66.5) radius 3 clockwise from (-30, 66.5) to (-27, 69.5)
  arc A5 centre (0, 47.5) radius 12.5 clockwise from (-10.0878, 54.8814) to (-7.5, 57.5)
  circle C1 centre (-16, 61.5) radius 2
  circle C2 centre (16, 61.5) radius 2
extrude "Extrude12" new body sketch "Sketch6" profile of L1 L2 L3 L4 C11 L5 L6 L7 L8 L9 L10 L11 L12 C12 L13 L14 L15 L16 L22 A3 L23 A4 L24 C14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 along normal blind 3
sketch "Sketch8" plane through (0, 0, 8) normal (0, 0, 1) x axis (1, 0, 0)
  line L1 (-25, 65.5) -> (-25, 57.5)
  line L2 (-22, 65.5) -> (-25, 65.5)
  line L3 (-22, 57.5) -> (-22, 65.5)
  line L4 (-25, 57.5) -> (-22, 57.5)
  line L5 (25, 65.5) -> (22, 65.5)
  line L6 (25, 57.5) -> (25, 65.5)
  line L7 (22, 57.5) -> (25, 57.5)
  line L8 (22, 65.5) -> (22, 57.5)
  line L9 (30, 54.8814) -> (10.0878, 54.8814)
  line L10 (30, 66.5) -> (30, 54.8814)
  line L11 (-27, 69.5) -> (27, 69.5)
  line L12 (-30, 54.8814) -> (-30, 66.5)
  line L13 (-10.0878, 54.8814) -> (-30, 54.8814)
  circle C1 centre (-16, 61.5) radius 2
  circle C2 centre (16, 61.5) radius 2
  arc A1 centre (27, 66.5) radius 3 clockwise from (27, 69.5) to (30, 66.5)
  arc A2 centre (-27, 66.5) radius 3 clockwise from (-30, 66.5) to (-27, 69.5)
  arc A3 centre (0, 47.5) radius 12.5 clockwise from (-10.0878, 54.8814) to (10.0878, 54.8814)
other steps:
create_component "CreateComponent1"
remove_body "RemoveBody1"
create_component "CreateComponent2"

design "Cup Holder"
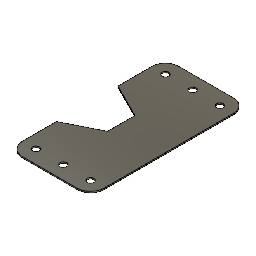
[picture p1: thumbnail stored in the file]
part number: carriage plate
parameter "Duese" = 0.4
parameter "d34" = 2.5
sketch "Sketch1" plane through (0, 0, 0) normal (0, 0, 1) x axis (1, 0, 0)
  line L1 (-20, 57.5) -> (20, 57.5)
  line L2 (-30, -47.5) -> (-30, 47.5)
  line L3 (20, -57.5) -> (-20, -57.5)
  line L4 (30, 47.5) -> (30, -47.5)
  line L5 (0, 22.5) -> (0, 1.75)
  line L6 (22.5, 0) -> (1.75, 0)
  line L7 (-5, 10) -> (-30, 22.5)
  line L8 (-5, -10) -> (-5, 10)
  line L9 (-30, -22.5) -> (-5, -10)
  circle C1 centre (0, 47.5) radius 2.46
  circle C2 centre (20, -47.5) radius 2.46
  circle C3 centre (0, -47.5) radius 2.46
  circle C4 centre (-20, -47.5) radius 2.46
  circle C5 centre (20, 47.5) radius 2.46
  circle C6 centre (-20, 47.5) radius 2.46
  arc A1 centre (20, 47.5) radius 10 clockwise from (20, 57.5) to (30, 47.5)
  arc A2 centre (-20, 47.5) radius 10 clockwise from (-30, 47.5) to (-20, 57.5)
  arc A3 centre (-20, -47.5) radius 10 clockwise from (-20, -57.5) to (-30, -47.5)
  arc A4 centre (20, -47.5) radius 10 clockwise from (30, -47.5) to (20, -57.5)
  circle C7 centre (-15, -20) radius 2
  circle C8 centre (15, -20) radius 2
  circle C9 centre (-15, 20) radius 2
  circle C10 centre (15, 20) radius 2
  point P1 (0, 0)
  point P2 (0, 0)
  point P4 (20, -47.5)
  point P5 (0, -47.5)
  point P6 (-20, -47.5)
  point P3 (0, 47.5)
  point P7 (20, 47.5)
  point P8 (-20, 47.5)
  point P9 (0, 0)
  point P10 (20, 57.5)
  point P16 (-30, -47.5)
  point P22 (-30, -47.5)
  point P23 (20, 57.5)
  point P32 (-30, 22.5)
  point P35 (-30, -22.5)
  point P24 (-15, -20)
  point P33 (-5, 10)
  point P34 (-5, -10)
  coincident P1 P2
  horizontal P4 P5
  horizontal P5 P6
  equal C2 C3
  equal C3 C4
  equal C4 C6
  equal C1 C6
  equal C1 C5
  vertical P2 P3
  horizontal P3 P7
  horizontal P3 P8
  vertical P1 P5
  vertical P4 P7
  vertical P6 P8
  perpendicular L1 L2
  parallel L1 L3
  parallel L2 L4
  horizontal L1
  coincident P1 P9
  tangent L4 A1
  coincident L1 P10
  tangent L2 A2
  tangent L3 A3
  coincident L2 P16
  tangent L3 A4
  coincident A3 P22
  coincident A1 P23
  tangent L1 A2
  tangent L1 A1
  tangent L4 A4
  tangent L2 A3
  equal A3 A4
  equal A1 A4
  equal A1 A2
  symmetric C7 L5 C8
  symmetric C7 L6 C9
  symmetric C8 L6 C10
  coincident L2 P32
  parallel L2 L8
  coincident L2 P35
  equal L7 L9
  dimension "d3" distance P2 P3 = 47.5 (= "( 95 / 2 ) * 1 mm")
  dimension "d4" distance P1 P5 = 47.5 (= "d3")
  dimension "d5" distance P4 P5 = 20
  dimension "d6" distance P5 P6 = 20 (= "d5")
  dimension "d7" diameter C1 = 4.92
  dimension "d8" distance P7 L1 = 10
  dimension "d9" distance P7 L4 = 10
  dimension "d10" distance P4 L3 = 10 (= "d8")
  dimension "d12" distance P6 L2 = 10 (= "d8")
  dimension "d13" radius A2 = 10
  dimension "d18" diameter C7 = 4
  dimension "d22" distance P9 P24 = 20
  dimension "d23" distance P2 P24 = 15
  dimension "d114" distance P33 P34 = 20
  dimension "d115" distance P1 P33 = 10 (= "d114 / 2")
  dimension "d116" distance P32 P35 = 45
  dimension "d117" distance L2 L8 = 25
  dimension "d24" AlongDistance = 5
  dimension "d25" TaperAngle = 0
  dimension "d30" AlongDistance = 0.25
  dimension "d31" distance = 7
  dimension "d32" AlongDistance = 6
  dimension "d33" TaperAngle = 0
  dimension "d40" AlongDistance = 4
  dimension "d41" TaperAngle = 0
  dimension "d42" AlongDistance = 0
  dimension "d43" distance = -2 (= "-( 0.4 * 5 ) * 1 mm")
  dimension "d45" TaperAngle = 0
  dimension "d48" distance = 75
  dimension "d49" AlongDistance = 140
  dimension "d50" TaperAngle = 0
  dimension "d51" AgainstDistance = 145
  dimension "d52" Side2TaperAngle = 0
  dimension "d53" diameter = 4.3
  dimension "d54" AlongDistance = 4.1
  dimension "d55" TaperAngle = 0
  dimension "d56" diameter = 11
  dimension "d63" leftDistance = 1.5
  dimension "d71" ChordLen = 0.5
  dimension "d75" diameter = 24
  dimension "d76" Side1Offset = 33.75
  dimension "d79" distance = 5
  dimension "d82" AlongDistance = 0
  dimension "d83" distance = -0.25
  dimension "d84" distance = -0.25 (= "( d83 )")
  dimension "d85" distance = -0.25 (= "( d83 )")
  dimension "d86" distance = -0.25 (= "( d83 )")
  dimension "d87" AlongDistance = -0.5
  dimension "d88" TaperAngle = -45
  dimension "d89" AlongDistance = 0
  dimension "d91" AlongAngle = 360
  dimension "d97" rightDistance = 4
  dimension "d99" distance = 2
  dimension "d100" distance = 100
  dimension "d101" distance = 4.5
  dimension "d103" distance = 4
  dimension "d104" distance = 35
  dimension "d105" distance = 17
  dimension "d109" distance = 53.5
  dimension "d110" distance = 3
  dimension "d111" distance = 74
  dimension "d112" distance = 110
  dimension "d113" distance = 45
extrude "Extrude11" new body sketch "Sketch1" profile of C1 C2 C3 C4 C5 C6 L1 L2 L3 L4 A1 A2 A3 A4 C7 C8 C9 C10 L7 L8 L9 along normal blind 1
